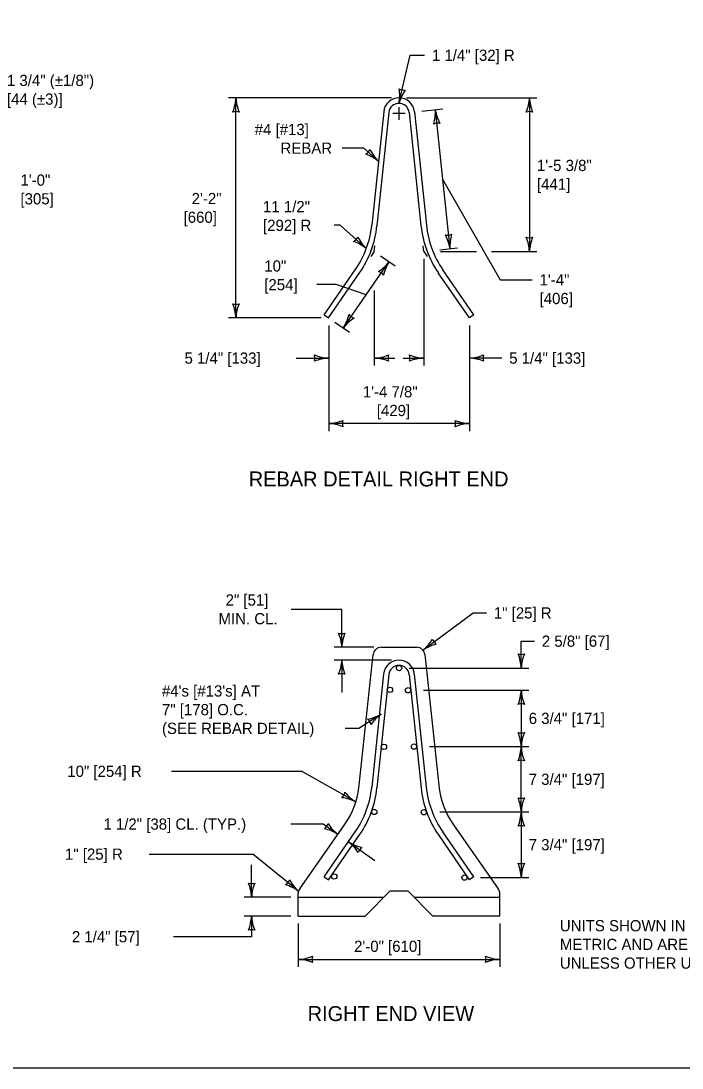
# Model space of a CAD drawing. Extents: x 49991.4 to 50021, y 49987.6 to 50011.4.
# Drawn here: x 50009.63 to 50013.17, y 49987.8 to 49993.4 of the extents above; entities that cross this region are included whole.
import ezdxf

# ---------------------------------------------------------------- set-up
doc = ezdxf.new("R2010")
doc.units = 0
for name, color, linetype in [('Level 1', 7, 'Continuous'), ('Level 2', 7, 'Continuous'), ('Level 3', 7, 'Continuous'), ('Level 4', 7, 'Continuous'), ('Level 6', 7, 'Continuous')]:
    doc.layers.add(name, color=color, linetype=linetype)

msp = doc.modelspace()

# ---------------------------------------------------------------- linework, layer by layer
at = {"layer": 'Level 1'}
for p, q in [((50011.57, 49992.916), (50011.506, 49992.3088)), ((50011.5977, 49992.9122), (50011.5338, 49992.306)), ((50011.7056, 49992.9122), (50011.7695, 49992.3061)), ((50011.7343, 49992.916), (50011.7982, 49992.309)), ((50011.2519, 49991.829), (50011.4179, 49992.0702)), ((50012.052, 49991.8292), (50011.8863, 49992.0703)), ((50011.2751, 49991.8131), (50011.4409, 49992.0542)), ((50012.0285, 49991.813), (50011.8624, 49992.0543)), ((50011.2519, 49991.829), (50011.2751, 49991.8131)), ((50012.052, 49991.8292), (50012.0285, 49991.813)), ((50011.5571, 49990.0507), (50011.7466, 49990.0507)), ((50011.4393, 49989.3121), (50011.5131, 49990.0111)), ((50011.7906, 49990.0111), (50011.8644, 49989.312)), ((50011.5697, 49989.9073), (50011.5059, 49989.3013)), ((50011.5979, 49989.9044), (50011.534, 49989.2982)), ((50011.7058, 49989.9044), (50011.7697, 49989.2982)), ((50011.7339, 49989.9073), (50011.7977, 49989.3013)), ((50011.1201, 49988.7579), (50011.3601, 49989.1005)), ((50011.9436, 49989.1004), (50012.1835, 49988.7579)), ((50011.2519, 49988.8213), (50011.4178, 49989.0627)), ((50011.2752, 49988.8053), (50011.4411, 49989.0465)), ((50011.8626, 49989.0465), (50012.0284, 49988.8053)), ((50012.0517, 49988.8213), (50011.8858, 49989.0627)), ((50011.2519, 49988.8213), (50011.2752, 49988.8053)), ((50012.0517, 49988.8213), (50012.0284, 49988.8053)), ((50011.1121, 49988.6121), (50011.1121, 49988.7325)), ((50011.4713, 49988.6121), (50011.6037, 49988.7465)), ((50011.6037, 49988.7465), (50011.6999, 49988.7465)), ((50011.8323, 49988.6121), (50011.6999, 49988.7465)), ((50012.1915, 49988.6121), (50012.1915, 49988.7325)), ((50011.1121, 49988.6121), (50011.4713, 49988.6121)), ((50012.1915, 49988.6121), (50011.8323, 49988.6121))]:
    msp.add_line(p, q, dxfattribs=at)
msp.add_lwpolyline([(49999.3835, 49998.9992), (50016.7501, 49998.9992), (50016.7501, 49987.7988), (49999.3835, 49987.7988)], close=True, dxfattribs=at)
for centre in [(50011.6519, 49989.9392), (50011.6035, 49989.8227), (50011.7004, 49989.8203), (50011.5714, 49989.5179), (50011.7322, 49989.519), (50011.5193, 49989.1692), (50011.785, 49989.1676), (50011.3052, 49988.824), (50012.0026, 49988.8179)]:
    msp.add_circle(centre, 0.0142, dxfattribs=at)
for centre, radius, start, end in [((50011.6521, 49992.908), 0.0825, 5.5788, 174.4212), ((50011.6517, 49992.907), 0.0542, 5.5788, 174.4212), ((50010.9921, 49992.3629), 0.5167, 325.491, 353.991), ((50010.9918, 49992.363), 0.545, 325.491, 353.991), ((50012.3116, 49992.3631), 0.545, 186.009, 214.509), ((50012.3121, 49992.3631), 0.5167, 186.009, 214.509), ((50011.5571, 49990.0064), 0.0442, 90, 173.9725), ((50011.7466, 49990.0064), 0.0442, 6.0275, 90), ((50011.6518, 49989.8993), 0.0825, 5.5788, 174.4212), ((50011.6518, 49989.8991), 0.0542, 5.5788, 174.4212), ((50010.9906, 49989.3594), 0.4512, 324.9777, 353.9725), ((50010.992, 49989.3554), 0.5167, 325.491, 353.991), ((50010.992, 49989.3553), 0.545, 325.491, 353.991), ((50012.3117, 49989.3553), 0.545, 186.009, 214.509), ((50012.3116, 49989.3554), 0.5167, 186.009, 214.509), ((50012.3132, 49989.3594), 0.4512, 186.0275, 215.0223), ((50011.1564, 49988.7325), 0.0442, 144.9777, 180), ((50012.1473, 49988.7325), 0.0442, 0, 35.0223)]:
    msp.add_arc(centre, radius, start, end, dxfattribs=at)
at = {"layer": 'Level 3'}
for p, q in [((50011.6518, 49992.9612), (50011.7117, 49993.2185)), ((50011.7117, 49993.2185), (50011.7882, 49993.2185)), ((50011.6122, 49992.9905), (50010.7387, 49992.9904)), ((50010.7787, 49991.813), (50010.7787, 49992.9904)), ((50011.6921, 49992.9905), (50012.3904, 49992.9905)), ((50012.3504, 49992.9905), (50012.3504, 49992.1684)), ((50011.6855, 49992.907), (50011.618, 49992.907)), ((50011.6518, 49992.9407), (50011.6518, 49992.8732)), ((50011.7742, 49992.9198), (50011.8861, 49992.9316)), ((50011.8463, 49992.9274), (50011.9248, 49992.1832)), ((50011.4633, 49992.7214), (50011.3469, 49992.7214)), ((50011.5421, 49992.651), (50011.4633, 49992.7214)), ((50011.3375, 49992.3086), (50011.3043, 49992.3086)), ((50011.4769, 49992.1841), (50011.3375, 49992.3086)), ((50011.506, 49992.3088), (50011.506, 49992.3088)), ((50011.5195, 49992.1684), (50011.5227, 49992.199)), ((50011.7841, 49992.1684), (50011.7809, 49992.199)), ((50011.8713, 49992.1775), (50011.9646, 49992.1874)), ((50011.5195, 49992.1684), (50011.5015, 49992.1422)), ((50011.5525, 49992.1457), (50011.6314, 49992.0913)), ((50011.7841, 49992.1684), (50011.8021, 49992.1422)), ((50011.7841, 49992.1284), (50011.7841, 49991.558)), ((50011.8734, 49992.1684), (50012.0665, 49992.1684)), ((50012.1465, 49992.1684), (50012.3904, 49992.1684)), ((50011.3537, 49991.7588), (50011.5984, 49992.1141)), ((50011.5197, 49991.9592), (50011.5197, 49991.5579)), ((50011.2351, 49991.813), (50010.7387, 49991.813)), ((50011.308, 49991.7903), (50011.387, 49991.736)), ((50011.2753, 49991.7731), (50011.2753, 49991.2076)), ((50011.3541, 49991.7588), (50011.3541, 49991.7588)), ((50012.0285, 49991.773), (50012.0285, 49991.2076)), ((50011.1019, 49991.5979), (50011.2753, 49991.5979)), ((50011.5197, 49991.5979), (50011.6301, 49991.5979)), ((50011.6738, 49991.598), (50011.7841, 49991.598)), ((50012.202, 49991.5979), (50012.0285, 49991.5979)), ((50012.0285, 49991.2476), (50011.2753, 49991.2476)), ((50011.3452, 49990.2535), (50011.0745, 49990.2535)), ((50011.3455, 49990.0507), (50011.3455, 49990.2535)), ((50011.7802, 49990.0352), (50012.0494, 49990.2343)), ((50012.0494, 49990.2343), (50012.1196, 49990.2343)), ((50011.5171, 49990.0507), (50011.3055, 49990.0507)), ((50012.3064, 49990.0833), (50012.3766, 49990.0833)), ((50012.3064, 49989.9393), (50012.3064, 49990.0833)), ((50011.6118, 49989.9818), (50011.3055, 49989.9819)), ((50011.3455, 49989.9819), (50011.3455, 49989.8084)), ((50011.7061, 49989.9393), (50012.3464, 49989.9393)), ((50011.783, 49989.8211), (50012.3464, 49989.8211)), ((50012.3063, 49989.8211), (50012.3063, 49989.5189)), ((50011.5568, 49989.6926), (50011.4369, 49989.6167)), ((50011.4369, 49989.6167), (50011.3631, 49989.6167)), ((50011.8148, 49989.5189), (50012.3463, 49989.5189)), ((50012.3063, 49989.1691), (50012.3063, 49989.5189)), ((50010.4344, 49989.3869), (50011.1289, 49989.3869)), ((50011.4207, 49989.2228), (50011.1289, 49989.3869)), ((50011.8697, 49989.1691), (50012.3463, 49989.1691)), ((50012.3063, 49989.1691), (50012.3063, 49988.8193)), ((50011.2461, 49989.1043), (50011.0731, 49989.1043)), ((50011.3244, 49989.0494), (50011.2461, 49989.1043)), ((50011.3813, 49989.0096), (50011.5233, 49988.9099)), ((50010.3144, 49988.9436), (50010.8688, 49988.9436)), ((50011.1138, 49988.7447), (50010.8688, 49988.9436)), ((50010.8625, 49988.7129), (50010.8625, 49988.8863)), ((50012.0889, 49988.8193), (50012.3463, 49988.8193)), ((50011.0721, 49988.7129), (50010.8226, 49988.7129)), ((50010.8625, 49988.7129), (50010.8625, 49988.7129)), ((50011.0721, 49988.6121), (50010.8226, 49988.6121)), ((50010.8625, 49988.6121), (50010.8625, 49988.5017)), ((50011.1121, 49988.5721), (50011.1121, 49988.3405)), ((50012.1915, 49988.5721), (50012.1915, 49988.3405)), ((50010.8625, 49988.5017), (50010.4448, 49988.5017)), ((50011.1121, 49988.3805), (50012.1915, 49988.3805))]:
    msp.add_line(p, q, dxfattribs=at)
for points in [[(50011.8856, 49992.5551), (50012.193, 49992.0169), (50012.3647, 49992.0169)], [(50011.4762, 49991.9364), (50011.3162, 49991.9909), (50011.211, 49991.9909)]]:
    msp.add_lwpolyline(points, dxfattribs=at)
for centre, radius, start, end in [((50011.4225, 49993.0028), 0.233, 349.7102, 8.96), ((50011.866, 49992.9018), 0.2223, 144.3389, 164.5224), ((50011.6809, 49993.086), 0.0548, 239.0217, 274.744), ((50010.5566, 49992.9996), 0.2223, 337.456, 357.6395), ((50011.0114, 49993.0019), 0.233, 182.8273, 202.0772), ((50012.1282, 49992.9996), 0.2223, 337.456, 357.6395), ((50012.5831, 49993.002), 0.233, 182.8273, 202.0772), ((50010.7787, 49992.8622), 0.0548, 72.1388, 107.8612), ((50011.6244, 49992.9133), 0.2223, 343.4623, 3.6458), ((50012.0765, 49992.9632), 0.233, 188.8336, 208.0834), ((50012.3504, 49992.8623), 0.0548, 72.1388, 107.8612), ((50011.8597, 49992.7999), 0.0548, 78.1451, 113.8674), ((50011.4465, 49992.7364), 0.0548, 300.3612, 336.0836), ((50011.3956, 49992.4698), 0.233, 51.0497, 70.2996), ((50011.6969, 49992.8105), 0.2223, 205.6784, 225.8619), ((50011.3813, 49992.2695), 0.0548, 300.3612, 336.0836), ((50011.6317, 49992.3436), 0.2223, 205.6784, 225.8619), ((50011.9114, 49992.3107), 0.0548, 258.1451, 293.8674), ((50011.6946, 49992.1474), 0.233, 8.8336, 28.0834), ((50012.1467, 49992.1973), 0.2223, 163.4623, 183.6458), ((50012.3504, 49992.2966), 0.0548, 252.1388, 287.8612), ((50012.1176, 49992.1569), 0.233, 2.8273, 22.0772), ((50012.5725, 49992.1592), 0.2223, 157.456, 177.6395), ((50011.3304, 49992.0029), 0.233, 51.0497, 70.2996), ((50011.4206, 49992.2474), 0.2223, 302.9494, 323.1329), ((50011.5258, 49992.0084), 0.0548, 37.6322, 73.3545), ((50011.7967, 49991.9917), 0.233, 148.3207, 167.5705), ((50010.7787, 49991.9412), 0.0548, 252.1388, 287.8612), ((50010.546, 49991.8015), 0.233, 2.8273, 22.0772), ((50011.0009, 49991.8038), 0.2223, 157.456, 177.6395), ((50011.1558, 49991.8811), 0.233, 328.2907, 347.5406), ((50011.5318, 49991.6251), 0.2223, 122.9194, 143.1029), ((50011.4267, 49991.8642), 0.0548, 217.6022, 253.3246), ((50011.2845, 49991.82), 0.2223, 247.456, 267.6395), ((50011.1471, 49991.5979), 0.0548, 342.1388, 17.8612), ((50011.5082, 49991.8306), 0.233, 272.8273, 292.0772), ((50011.648, 49991.5979), 0.0548, 162.1388, 197.8612), ((50011.7933, 49991.8201), 0.2223, 247.456, 267.6395), ((50011.6559, 49991.598), 0.0548, 342.1388, 17.8612), ((50012.017, 49991.8307), 0.233, 272.8273, 292.0772), ((50012.1568, 49991.5979), 0.0548, 162.1388, 197.8612), ((50011.2868, 49991.3651), 0.233, 92.8273, 112.0772), ((50011.5106, 49991.3758), 0.2223, 67.456, 87.6395), ((50011.7956, 49991.3653), 0.233, 92.8273, 112.0772), ((50012.0194, 49991.3758), 0.2223, 67.456, 87.6395), ((50011.2638, 49991.4804), 0.233, 272.8273, 292.0772), ((50011.2662, 49991.0255), 0.2223, 67.456, 87.6395), ((50011.4036, 49991.2476), 0.0548, 162.1388, 197.8612), ((50012.0377, 49991.4698), 0.2223, 247.456, 267.6395), ((50011.9003, 49991.2476), 0.0548, 342.1388, 17.8612), ((50012.04, 49991.0149), 0.233, 92.8273, 112.0772), ((50011.3455, 49990.1789), 0.0548, 252.1388, 287.8612), ((50011.1128, 49990.0392), 0.233, 2.8273, 22.0772), ((50011.5676, 49990.0415), 0.2223, 157.456, 177.6395), ((50011.6326, 49990.2155), 0.233, 309.3046, 328.5545), ((50011.9049, 49989.8512), 0.2223, 103.9333, 124.1168), ((50011.8833, 49990.1114), 0.0548, 198.6161, 234.3385), ((50012.3064, 49990.0675), 0.0548, 252.1388, 287.8612), ((50012.0737, 49989.9278), 0.233, 2.8273, 22.0772), ((50012.5285, 49989.9301), 0.2223, 157.456, 177.6395), ((50011.1234, 49989.991), 0.2223, 337.456, 357.6395), ((50011.5782, 49989.9934), 0.233, 182.8273, 202.0772), ((50011.3455, 49989.8537), 0.0548, 72.1388, 107.8612), ((50012.0842, 49989.8303), 0.2223, 337.456, 357.6395), ((50012.5391, 49989.8326), 0.233, 182.8273, 202.0772), ((50012.3063, 49989.6929), 0.0548, 72.1388, 107.8612), ((50011.4456, 49989.8854), 0.2226, 279.7843, 299.9678), ((50011.4483, 49989.624), 0.0548, 14.4671, 50.1895), ((50011.6911, 49989.5019), 0.2333, 125.1556, 144.4054), ((50012.3063, 49989.6471), 0.0548, 252.1388, 287.8612), ((50012.0736, 49989.5074), 0.233, 2.8273, 22.0772), ((50012.5284, 49989.5097), 0.2223, 157.456, 177.6395), ((50012.0842, 49989.528), 0.2223, 337.456, 357.6395), ((50012.539, 49989.5304), 0.233, 182.8273, 202.0772), ((50012.3063, 49989.3907), 0.0548, 72.1388, 107.8612), ((50011.3089, 49989.2857), 0.0548, 312.7819, 348.5043), ((50011.5375, 49989.412), 0.2223, 218.0991, 238.2826), ((50011.3166, 49989.0144), 0.233, 63.4704, 82.7203), ((50012.3063, 49989.2973), 0.0548, 252.1388, 287.8612), ((50012.0736, 49989.1576), 0.233, 2.8273, 22.0772), ((50012.5284, 49989.1599), 0.2223, 157.456, 177.6395), ((50012.0842, 49989.1782), 0.2223, 337.456, 357.6395), ((50012.539, 49989.1806), 0.233, 182.8273, 202.0772), ((50011.2194, 49989.123), 0.0548, 307.1173, 342.8397), ((50011.4673, 49989.2334), 0.233, 212.9013, 232.1512), ((50012.3063, 49989.0409), 0.0548, 72.1388, 107.8612), ((50011.2044, 49988.8623), 0.2223, 57.339, 77.5225), ((50011.5013, 49989.1967), 0.2223, 237.344, 257.5275), ((50011.2383, 49988.8256), 0.233, 32.9063, 52.1562), ((50011.4863, 49988.936), 0.0548, 127.1223, 162.8447), ((50012.3063, 49988.9475), 0.0548, 252.1388, 287.8612), ((50012.0736, 49988.8078), 0.233, 2.8273, 22.0772), ((50012.5284, 49988.8101), 0.2223, 157.456, 177.6395), ((50010.6404, 49988.7037), 0.2223, 2.3605, 22.544), ((50010.8625, 49988.8411), 0.0548, 252.1388, 287.8612), ((50011.0952, 49988.7014), 0.233, 157.9228, 177.1727), ((50011.0143, 49988.8255), 0.0548, 303.0879, 338.8102), ((50010.9762, 49988.5568), 0.233, 53.7764, 73.0262), ((50011.2609, 49988.9115), 0.2223, 208.4051, 228.5886), ((50010.6298, 49988.6236), 0.233, 337.9228, 357.1727), ((50011.0846, 49988.6212), 0.2223, 182.3605, 202.544), ((50010.8625, 49988.4839), 0.0548, 72.1388, 107.8612), ((50011.1006, 49988.6132), 0.233, 272.8273, 292.0772), ((50011.103, 49988.1584), 0.2223, 67.456, 87.6395), ((50011.2403, 49988.3805), 0.0548, 162.1388, 197.8612), ((50012.2007, 49988.6026), 0.2223, 247.456, 267.6395), ((50012.0633, 49988.3805), 0.0548, 342.1388, 17.8612), ((50012.203, 49988.1478), 0.233, 92.8273, 112.0772)]:
    msp.add_arc(centre, radius, start, end, dxfattribs=at)
at = {"layer": 'Level 4'}
for p, q in [((50011.1121, 49988.7129), (50011.5706, 49988.7129)), ((50011.733, 49988.7129), (50012.1915, 49988.7129))]:
    msp.add_line(p, q, dxfattribs=at)
at = {"layer": 'Level 6'}
msp.add_line((50012.3063, 49988.9942), (50012.3063, 49988.9942), dxfattribs=at)
msp.add_line((50012.3063, 49988.9942), (50012.3063, 49988.9942), dxfattribs=at)

# ---------------------------------------------------------------- texts
at = {"layer": 'Level 2'}
for s, height, p in [('1 1/4" [32] R', 0.06, (50011.8282, 49993.1885)), ('1 3/4" (±1/8")', 0.06, (50009.5526, 49993.0539)), ('[44 (±3)]', 0.06, (50009.5526, 49992.9539)), ('#4 [#13]', 0.06, (50010.8792, 49992.7914)), ('REBAR', 0.06, (50011.0173, 49992.6914)), ('1\'-5 3/8"', 0.06, (50012.3904, 49992.5989)), ('1\'-0" ', 0.06, (50009.6249, 49992.5204)), ('[441]', 0.06, (50012.3904, 49992.4989)), ('[305]', 0.06, (50009.6249, 49992.4204)), ('2\'-2"', 0.06, (50010.5418, 49992.4217)), ('11 1/2"', 0.06, (50010.9238, 49992.3785)), ('[660]', 0.06, (50010.4983, 49992.3217)), ('[292] R', 0.06, (50010.9238, 49992.2785)), ('10"', 0.06, (50010.9305, 49992.0609)), ('[254]', 0.06, (50010.9305, 49991.9609)), ('1\'-4"', 0.06, (50012.4047, 49991.9869)), ('[406]', 0.06, (50012.4047, 49991.8869)), ('5 1/4" [133]', 0.06, (50010.5035, 49991.5679)), ('5 1/4" [133]', 0.06, (50012.242, 49991.5679)), ('1\'-4 7/8"', 0.06, (50011.458, 49991.3876)), ('[429]', 0.06, (50011.533, 49991.2876)), ('REBAR DETAIL RIGHT END', 0.08, (50010.8473, 49990.9111)), ('2" [51] ', 0.06, (50010.7234, 49990.2735)), ('1" [25] R', 0.06, (50012.1596, 49990.2043)), ('MIN. CL. ', 0.06, (50010.6854, 49990.1735)), ('2 5/8" [67]', 0.06, (50012.4166, 49990.0533)), ("#4's [#13's] AT ", 0.06, (50010.3826, 49989.7867)), ('7" [178] O.C.', 0.06, (50010.3826, 49989.6867)), ('6 3/4" [171]', 0.06, (50012.3464, 49989.64)), ('(SEE REBAR DETAIL)', 0.06, (50010.3826, 49989.5867)), ('10" [254] R', 0.06, (50009.8755, 49989.3569)), ('7 3/4" [197]', 0.06, (50012.3463, 49989.314)), ('1 1/2" [38] CL. (TYP.)', 0.06, (50010.0692, 49989.0743)), ('7 3/4" [197]', 0.06, (50012.3463, 49988.9642)), ('1" [25] R', 0.06, (50009.8633, 49988.9136)), ('UNITS SHOWN IN BRACKETS [] ARE ', 0.06, (50012.5132, 49988.5305)), ('2 1/4" [57]', 0.06, (50009.9003, 49988.4717)), ('2\'-0" [610]', 0.06, (50011.4112, 49988.4205)), ('METRIC AND ARE IN MILLIMETERS (mm) ', 0.06, (50012.5132, 49988.4305)), ('UNLESS OTHER UNITS ARE SHOWN.', 0.06, (50012.5132, 49988.3305)), ('RIGHT END VIEW', 0.08, (50011.1626, 49988.0504))]:
    msp.add_text(s, height=height, dxfattribs=at).set_placement(p)

doc.saveas('drawing.dxf')
